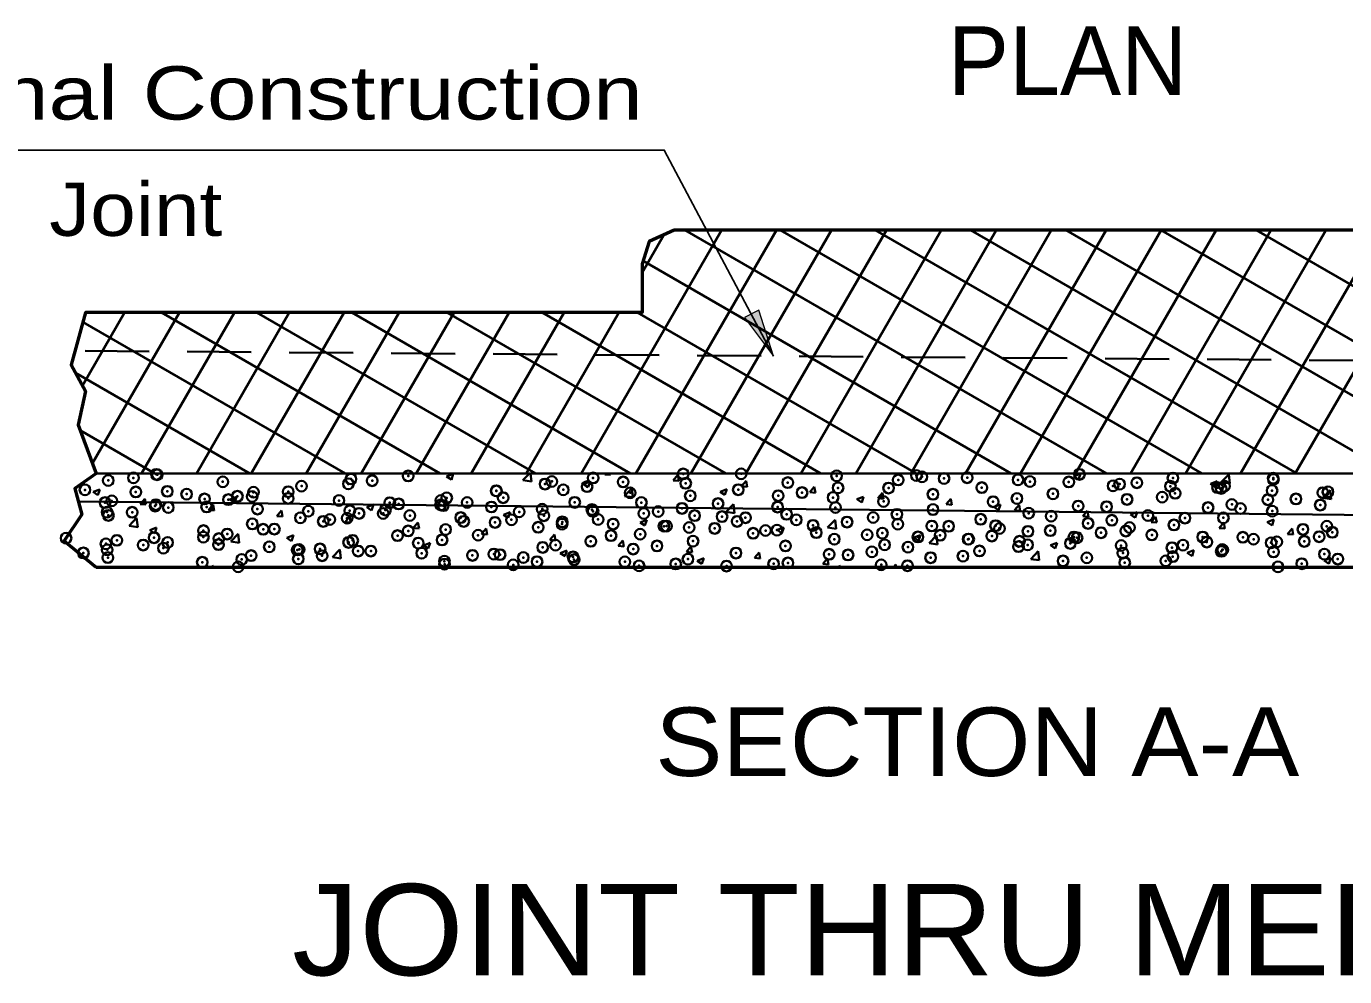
# Model space of a CAD drawing. Extents: x 14 to 49.3, y 28 to 50.
# Drawn here: x 18.676 to 22.139, y 39.449 to 41.946 of the extents above; entities that cross this region are included whole.
import ezdxf

# ---------------------------------------------------------------- set-up
doc = ezdxf.new("R2010")
doc.units = 0
doc.header["$LTSCALE"] = 0.056
doc.header["$PDMODE"] = 32
doc.header["$PDSIZE"] = 0.028
doc.linetypes.add('MEDIUM_DASHED', pattern=[4.5, 3, -1.5])
for name, color, linetype, lineweight in [('1', 7, 'Continuous', 35), ('2', 7, 'MEDIUM_DASHED', 35), ('3', 7, 'Continuous', 13)]:
    doc.layers.add(name, color=color, linetype=linetype, lineweight=lineweight)

msp = doc.modelspace()

# ---------------------------------------------------------------- hatches: boundary and pattern name
at = {"layer": '3'}
msp.add_hatch(color=256, dxfattribs=at).paths.add_polyline_path([(20.59983, 41.20042), (20.56292, 41.18133), (20.63883, 41.07983), (20.63883, 41.07983)])

# ---------------------------------------------------------------- linework, layer by layer
at = {"layer": '1', "lineweight": 40}
for p, q in [((20.13308, 40.77142), (20.50208, 41.41067)), ((20.27742, 40.77142), (20.6465, 41.41067)), ((20.29342, 41.29925), (20.35075, 41.3985)), ((20.40617, 41.41067), (21.51342, 40.77142)), ((20.42175, 40.77142), (20.79083, 41.41067)), ((20.56608, 40.77142), (20.93517, 41.41067)), ((20.65617, 41.41067), (21.76342, 40.77142)), ((20.71042, 40.77142), (21.0795, 41.41067)), ((20.85475, 40.77142), (21.22383, 41.41067)), ((20.90617, 41.41067), (22.01342, 40.77142)), ((20.99908, 40.77142), (21.36817, 41.41067)), ((21.14342, 40.77142), (21.5125, 41.41067)), ((21.15617, 41.41067), (22.26342, 40.77142)), ((21.28775, 40.77142), (21.65683, 41.41067)), ((21.40617, 41.41067), (22.51342, 40.77142)), ((21.43208, 40.77142), (21.80117, 41.41067)), ((21.57642, 40.77142), (21.9455, 41.41067)), ((21.65617, 41.41067), (22.76342, 40.77142)), ((21.72075, 40.77142), (22.08983, 41.41067)), ((21.86508, 40.77142), (22.23417, 41.41067)), ((21.90617, 41.41067), (23.01342, 40.77142)), ((22.00942, 40.77142), (22.3785, 41.41067)), ((20.29592, 41.33), (21.26342, 40.77142)), ((18.82317, 41.00267), (18.93383, 41.19433)), ((18.8495, 40.79833), (19.07817, 41.19433)), ((18.97833, 40.77142), (19.2225, 41.19433)), ((19.03092, 41.19433), (19.76342, 40.77142)), ((19.12267, 40.77142), (19.36683, 41.19433)), ((19.267, 40.77142), (19.51117, 41.19433)), ((19.28092, 41.19433), (20.01342, 40.77142)), ((19.41133, 40.77142), (19.6555, 41.19433)), ((19.53092, 41.19433), (20.26342, 40.77142)), ((19.55575, 40.77142), (19.79983, 41.19433)), ((19.70008, 40.77142), (19.94417, 41.19433)), ((19.78092, 41.19433), (20.51342, 40.77142)), ((19.84442, 40.77142), (20.0885, 41.19433)), ((19.98875, 40.77142), (20.23283, 41.19433)), ((20.03092, 41.19433), (20.76342, 40.77142)), ((20.28092, 41.19433), (21.01342, 40.77142)), ((18.82442, 41.16925), (19.51342, 40.77142)), ((18.80492, 41.03617), (19.26342, 40.77142)), ((18.818, 40.88425), (19.01342, 40.77142))]:
    msp.add_line(p, q, dxfattribs=at)
at = {"layer": '1'}
for p, q in [((23.80842, 40.77142), (18.85933, 40.77142)), ((19.78008, 40.7635), (19.79758, 40.77025)), ((19.78008, 40.7635), (19.7925, 40.75517)), ((19.79258, 40.75508), (19.79758, 40.77025)), ((19.98042, 40.7535), (19.99767, 40.77142)), ((20.00267, 40.75008), (20.00017, 40.77142)), ((20.00267, 40.75008), (20.00017, 40.77142)), ((20.19575, 40.769), (20.19792, 40.77142)), ((20.19575, 40.769), (20.21075, 40.76767)), ((20.21075, 40.76767), (20.21, 40.77142)), ((20.37508, 40.75325), (20.38717, 40.76767)), ((20.39008, 40.752), (20.38717, 40.76767)), ((21.42725, 40.76408), (21.44475, 40.77075)), ((21.42725, 40.76408), (21.43975, 40.75567)), ((21.43975, 40.75567), (21.44483, 40.77075)), ((21.815, 40.74875), (21.83442, 40.76908)), ((21.83725, 40.74533), (21.83442, 40.769)), ((18.8515, 40.72292), (18.869, 40.72967)), ((18.86392, 40.7145), (18.869, 40.72967)), ((19.98042, 40.7535), (20.00267, 40.75008)), ((20.13942, 40.7435), (20.15692, 40.75025)), ((20.13942, 40.7435), (20.15183, 40.73508)), ((20.15183, 40.73508), (20.15692, 40.75025)), ((20.24725, 40.71208), (20.26675, 40.73242)), ((20.2695, 40.70867), (20.26675, 40.73242)), ((20.37508, 40.75325), (20.39, 40.752)), ((20.49867, 40.7235), (20.51617, 40.73017)), ((20.49867, 40.7235), (20.51108, 40.71508)), ((20.51108, 40.71508), (20.51617, 40.73017)), ((20.55442, 40.73758), (20.5665, 40.75192)), ((20.55442, 40.73758), (20.56933, 40.73625)), ((20.56933, 40.73625), (20.5665, 40.75192)), ((20.73375, 40.72192), (20.74575, 40.73625)), ((20.74867, 40.72058), (20.74575, 40.73625)), ((21.78658, 40.744), (21.80408, 40.75075)), ((21.78658, 40.744), (21.799, 40.73567)), ((21.799, 40.73567), (21.80408, 40.75075)), ((21.815, 40.74875), (21.83717, 40.74533)), ((22.08175, 40.70733), (22.10125, 40.72767)), ((22.104, 40.70392), (22.10125, 40.72767)), ((18.80667, 40.71917), (18.808, 40.72075)), ((18.81092, 40.70508), (18.808, 40.72075)), ((18.81042, 40.70517), (18.81092, 40.70508)), ((23.81192, 40.64508), (18.81242, 40.69783)), ((18.8515, 40.72292), (18.86392, 40.7145)), ((18.97525, 40.69075), (18.98733, 40.70508)), ((18.97525, 40.69075), (18.99025, 40.68942)), ((18.99025, 40.68942), (18.98733, 40.70508)), ((19.15458, 40.67508), (19.16667, 40.68942)), ((19.1695, 40.67375), (19.16667, 40.68942)), ((19.21075, 40.70292), (19.22825, 40.70958)), ((19.21075, 40.70292), (19.22317, 40.6945)), ((19.22325, 40.6945), (19.22825, 40.70958)), ((19.57008, 40.68292), (19.58758, 40.68958)), ((19.5825, 40.6745), (19.58758, 40.68958)), ((20.24725, 40.71208), (20.2695, 40.70867)), ((20.51408, 40.67075), (20.5335, 40.691)), ((20.53633, 40.66725), (20.53358, 40.691)), ((20.73375, 40.72192), (20.74867, 40.72058)), ((20.85792, 40.70342), (20.87542, 40.71017)), ((20.85792, 40.70342), (20.87042, 40.69508)), ((20.87042, 40.69508), (20.8755, 40.71017)), ((20.91308, 40.70625), (20.92508, 40.72058)), ((20.91308, 40.70625), (20.928, 40.70492)), ((20.928, 40.70492), (20.92508, 40.72058)), ((21.09233, 40.6905), (21.10442, 40.70492)), ((21.09233, 40.6905), (21.10733, 40.68925)), ((21.10733, 40.68925), (21.10442, 40.70492)), ((21.21725, 40.68342), (21.23475, 40.69017)), ((21.22967, 40.675), (21.23475, 40.69017)), ((21.27167, 40.67483), (21.28375, 40.68917)), ((21.28667, 40.6735), (21.28375, 40.68917)), ((22.08175, 40.70733), (22.104, 40.70392)), ((18.94633, 40.63408), (18.96583, 40.65442)), ((18.96858, 40.63067), (18.96583, 40.65442)), ((19.15458, 40.67508), (19.1695, 40.67375)), ((19.33392, 40.65933), (19.34592, 40.67375)), ((19.33392, 40.65933), (19.34883, 40.65808)), ((19.34883, 40.65808), (19.346, 40.67375)), ((19.51325, 40.64367), (19.52525, 40.658)), ((19.52817, 40.64233), (19.52525, 40.658)), ((19.57008, 40.68292), (19.5825, 40.6745)), ((19.92933, 40.66283), (19.94683, 40.66958)), ((19.92933, 40.66283), (19.94175, 40.6545)), ((19.94175, 40.6545), (19.94683, 40.66958)), ((20.51408, 40.67075), (20.53633, 40.66725)), ((21.21725, 40.68342), (21.22967, 40.675)), ((21.27167, 40.67483), (21.28658, 40.6735)), ((21.451, 40.65917), (21.463, 40.6735)), ((21.451, 40.65917), (21.46592, 40.65783)), ((21.46592, 40.65783), (21.46308, 40.6735)), ((21.5765, 40.66342), (21.594, 40.67008)), ((21.5765, 40.66342), (21.58892, 40.655)), ((21.589, 40.655), (21.594, 40.67008)), ((21.63033, 40.6435), (21.64233, 40.65783)), ((21.64525, 40.64217), (21.64233, 40.65783)), ((18.94633, 40.63408), (18.96858, 40.63067)), ((19.00075, 40.62225), (19.01825, 40.629)), ((19.00075, 40.62225), (19.01317, 40.61392)), ((19.01317, 40.61392), (19.01825, 40.629)), ((19.51325, 40.64367), (19.52817, 40.64233)), ((19.6925, 40.628), (19.70458, 40.64233)), ((19.6925, 40.628), (19.7075, 40.62667)), ((19.7075, 40.62667), (19.70458, 40.64233)), ((19.87183, 40.61233), (19.88392, 40.62667)), ((19.88683, 40.611), (19.88392, 40.62667)), ((20.28858, 40.64283), (20.30608, 40.64958)), ((20.28858, 40.64283), (20.30108, 40.63442)), ((20.30108, 40.63442), (20.30617, 40.64958)), ((20.64792, 40.62283), (20.66542, 40.6295)), ((20.64792, 40.62283), (20.66033, 40.61442)), ((20.66033, 40.61442), (20.66542, 40.6295)), ((20.78083, 40.62933), (20.80033, 40.64967)), ((20.78083, 40.62933), (20.80308, 40.62592)), ((20.80308, 40.62592), (20.80033, 40.64967)), ((21.63033, 40.6435), (21.64525, 40.64217)), ((21.80958, 40.62775), (21.82167, 40.64217)), ((21.80958, 40.62775), (21.82458, 40.6265)), ((21.82458, 40.6265), (21.82167, 40.64217)), ((21.93583, 40.64342), (21.95333, 40.65008)), ((21.93583, 40.64342), (21.94825, 40.635)), ((21.94825, 40.635), (21.95333, 40.65008)), ((21.98892, 40.61208), (22.001, 40.62642)), ((22.00392, 40.61075), (22.001, 40.62642)), ((19.21317, 40.59275), (19.23267, 40.613)), ((19.21317, 40.59275), (19.23542, 40.58925)), ((19.23542, 40.58925), (19.23267, 40.613)), ((19.36, 40.60225), (19.3775, 40.609)), ((19.36, 40.60225), (19.37242, 40.59383)), ((19.37242, 40.59383), (19.3775, 40.609)), ((19.71925, 40.58225), (19.73675, 40.58892)), ((19.73175, 40.57383), (19.73675, 40.58892)), ((19.87183, 40.61233), (19.88675, 40.611)), ((20.05117, 40.59658), (20.06325, 40.611)), ((20.05117, 40.59658), (20.06608, 40.59533)), ((20.06608, 40.59533), (20.06325, 40.611)), ((20.2305, 40.58092), (20.2425, 40.59525)), ((20.24542, 40.57958), (20.2425, 40.59525)), ((21.00717, 40.60283), (21.02467, 40.6095)), ((21.00717, 40.60283), (21.01958, 40.59442)), ((21.01958, 40.59442), (21.02467, 40.6095)), ((21.04767, 40.588), (21.06717, 40.60825)), ((21.04767, 40.588), (21.06992, 40.5845)), ((21.06992, 40.5845), (21.06717, 40.60825)), ((21.3665, 40.58275), (21.384, 40.5895)), ((21.37892, 40.57442), (21.384, 40.5895)), ((21.98892, 40.61208), (22.00392, 40.61075)), ((19.48, 40.55133), (19.49942, 40.57167)), ((19.48, 40.55133), (19.50217, 40.54792)), ((19.50225, 40.54792), (19.49942, 40.57167)), ((19.71925, 40.58225), (19.73175, 40.57383)), ((20.07858, 40.56217), (20.09608, 40.56892)), ((20.07858, 40.56217), (20.091, 40.55383)), ((20.091, 40.55383), (20.09608, 40.56892)), ((20.2305, 40.58092), (20.24542, 40.57958)), ((20.40975, 40.56525), (20.42183, 40.57958)), ((20.40975, 40.56525), (20.42475, 40.56392)), ((20.42475, 40.56392), (20.42183, 40.57958)), ((20.58908, 40.5495), (20.60117, 40.56392)), ((20.60408, 40.54825), (20.60117, 40.56392)), ((21.3145, 40.54658), (21.334, 40.56692)), ((21.33675, 40.54317), (21.334, 40.56692)), ((21.3665, 40.58275), (21.37892, 40.57442)), ((21.72575, 40.56275), (21.74325, 40.5695)), ((21.72575, 40.56275), (21.73817, 40.55433)), ((21.73817, 40.55433), (21.74325, 40.5695)), ((19.16033, 40.52558), (19.16742, 40.52833)), ((19.1665, 40.52558), (19.16742, 40.52833)), ((19.76175, 40.52558), (19.76625, 40.53025)), ((19.76683, 40.52558), (19.76625, 40.53025)), ((20.43783, 40.54217), (20.45533, 40.54892)), ((20.43783, 40.54217), (20.45025, 40.53383)), ((20.45025, 40.53383), (20.45533, 40.54892)), ((20.58908, 40.5495), (20.60408, 40.54825)), ((20.76842, 40.53383), (20.7805, 40.54825)), ((20.76842, 40.53383), (20.78333, 40.53258)), ((20.78333, 40.53258), (20.7805, 40.54825)), ((20.80608, 40.52558), (20.81458, 40.52892)), ((20.8135, 40.52558), (20.81467, 40.52892)), ((20.954, 40.52558), (20.95975, 40.5325)), ((20.96108, 40.52558), (20.95983, 40.5325)), ((21.3145, 40.54658), (21.33675, 40.54317)), ((22.085, 40.54275), (22.1025, 40.54942)), ((22.085, 40.54275), (22.0975, 40.53433)), ((22.0975, 40.53433), (22.1025, 40.54942))]:
    msp.add_line(p, q, dxfattribs=at)
at = {"layer": '1', "lineweight": 53}
msp.add_line((18.85933, 40.52558), (23.81775, 40.52558), dxfattribs=at)
for points in [[(23.799, 41.17467), (22.55233, 41.17467), (22.55233, 41.35167), (22.52425, 41.37133), (22.48675, 41.41067), (20.37783, 41.41067), (20.31217, 41.38117), (20.29342, 41.32217), (20.29342, 41.19433), (18.83125, 41.19433), (18.79375, 41.05667), (18.83125, 40.98783), (18.8125, 40.89933), (18.85933, 40.77142)], [(18.85933, 40.77142), (18.80308, 40.73208), (18.82183, 40.66325), (18.775, 40.59442), (18.85933, 40.52558)]]:
    msp.add_lwpolyline(points, dxfattribs=at)
at = {"layer": '1'}
for p in [(18.89117, 40.75292), (18.95733, 40.75975), (19.0175, 40.76892), (19.01992, 40.768), (19.19217, 40.74942), (19.52192, 40.74408), (19.52875, 40.75683), (19.5845, 40.75233), (19.67917, 40.76483), (20.05658, 40.75042), (20.16483, 40.75958), (20.24375, 40.74917), (20.40158, 40.77), (20.40808, 40.74558), (20.55392, 40.77058), (20.67617, 40.74742), (20.8045, 40.765), (20.96617, 40.75433), (21.01408, 40.76592), (21.02875, 40.76258), (21.08675, 40.75817), (21.1475, 40.76025), (21.281, 40.75458), (21.31225, 40.75017), (21.41442, 40.749), (21.44208, 40.76892), (21.59325, 40.747), (21.688, 40.75942), (21.95125, 40.75917), (21.95183, 40.75567), (18.83008, 40.72833), (18.9635, 40.72275), (19.04633, 40.72442), (19.097, 40.71708), (19.23042, 40.71142), (19.26933, 40.71083), (19.27267, 40.72208), (19.364, 40.72333), (19.39892, 40.73808), (19.91025, 40.72592), (19.91083, 40.72542), (20.03858, 40.74358), (20.08642, 40.7285), (20.149, 40.73675), (20.26233, 40.72058), (20.42, 40.71267), (20.54625, 40.72867), (20.651, 40.71283), (20.71358, 40.72108), (20.80825, 40.73358), (20.941, 40.73317), (21.05758, 40.71658), (21.18592, 40.73417), (21.37283, 40.71792), (21.53067, 40.73875), (21.54792, 40.74333), (21.68133, 40.73767), (21.69367, 40.71925), (21.80542, 40.73417), (21.81475, 40.73208), (21.8235, 40.738), (21.94825, 40.72642), (22.08167, 40.72075), (22.09525, 40.72308), (18.88283, 40.69475), (18.90058, 40.69942), (19.01442, 40.68575), (19.01625, 40.68917), (19.04883, 40.68183), (19.14425, 40.7045), (19.14967, 40.6835), (19.20675, 40.70258), (19.28317, 40.67783), (19.36392, 40.70583), (19.49733, 40.70017), (19.61925, 40.67533), (19.63083, 40.6945), (19.65408, 40.69117), (19.76425, 40.68892), (19.765, 40.70033), (19.77133, 40.687), (19.78033, 40.70717), (19.83392, 40.69525), (19.89775, 40.68325), (19.92858, 40.70767), (20.03117, 40.67758), (20.1165, 40.6955), (20.16183, 40.67633), (20.29167, 40.69508), (20.39842, 40.67958), (20.49308, 40.69208), (20.64942, 40.68308), (20.79517, 40.70817), (20.80142, 40.68183), (20.92775, 40.69783), (21.05767, 40.6765), (21.21558, 40.69725), (21.27817, 40.7055), (21.439, 40.68567), (21.51383, 40.68408), (21.56742, 40.70325), (21.65967, 40.70917), (21.78008, 40.68167), (21.84267, 40.68983), (21.86533, 40.67925), (21.93733, 40.70233), (22.01117, 40.70433), (22.07508, 40.68842), (18.88817, 40.66975), (18.89158, 40.66117), (18.95417, 40.66933), (19.39592, 40.65483), (19.41658, 40.67225), (19.45617, 40.6455), (19.47342, 40.65033), (19.51875, 40.65375), (19.52575, 40.67358), (19.55008, 40.66658), (19.61342, 40.66625), (19.6835, 40.66092), (19.817, 40.65533), (19.82492, 40.6455), (19.90717, 40.64275), (19.95042, 40.64967), (19.97075, 40.6705), (20.0355, 40.66033), (20.08392, 40.644), (20.16467, 40.672), (20.17792, 40.65058), (20.29808, 40.66633), (20.33583, 40.67142), (20.43158, 40.66067), (20.50358, 40.65808), (20.54325, 40.64542), (20.565, 40.65508), (20.67308, 40.66417), (20.6985, 40.64942), (20.83192, 40.64375), (20.90042, 40.65575), (20.963, 40.664), (21.18292, 40.65092), (21.30917, 40.66692), (21.368, 40.65908), (21.46492, 40.64017), (21.5275, 40.64842), (21.62217, 40.66083), (21.7195, 40.65425), (21.8205, 40.65483), (21.94883, 40.67242), (19.14125, 40.62125), (19.20358, 40.61225), (19.26958, 40.63883), (19.29825, 40.62475), (19.32758, 40.62525), (19.65108, 40.608), (19.67908, 40.62042), (19.77733, 40.624), (19.86283, 40.60908), (20.02067, 40.62992), (20.08325, 40.63817), (20.212, 40.608), (20.21733, 40.63842), (20.28858, 40.61183), (20.35083, 40.63275), (20.35775, 40.63308), (20.417, 40.62942), (20.48425, 40.62708), (20.58525, 40.61425), (20.61775, 40.6215), (20.64783, 40.6225), (20.7425, 40.635), (20.75117, 40.61583), (20.88467, 40.61017), (20.92467, 40.61458), (20.96533, 40.63817), (21.0545, 40.63333), (21.07642, 40.609), (21.09883, 40.6325), (21.21233, 40.60692), (21.22225, 40.63408), (21.23225, 40.62683), (21.30708, 40.61933), (21.36575, 40.62125), (21.49917, 40.61558), (21.56433, 40.62008), (21.57375, 40.62925), (21.63267, 40.60992), (21.69058, 40.63608), (22.0295, 40.6245), (22.09208, 40.63275), (22.10658, 40.61683), (18.78033, 40.60125), (18.88508, 40.5865), (18.88842, 40.57075), (18.91383, 40.59567), (18.98308, 40.58325), (19.01142, 40.6025), (19.036, 40.57525), (19.04725, 40.59), (19.141, 40.604), (19.18075, 40.58433), (19.18183, 40.60025), (19.31417, 40.57875), (19.39283, 40.57167), (19.44758, 40.57308), (19.52267, 40.59033), (19.53333, 40.59542), (19.7055, 40.58842), (19.76808, 40.59667), (20.0325, 40.57708), (20.06617, 40.583), (20.15875, 40.59308), (20.27008, 40.57275), (20.33267, 40.581), (20.42733, 40.5935), (20.67008, 40.581), (20.79842, 40.59858), (20.93067, 40.584), (20.99192, 40.57783), (21.01808, 40.60458), (21.14975, 40.59867), (21.1515, 40.59892), (21.28217, 40.57917), (21.285, 40.59325), (21.30617, 40.58375), (21.41842, 40.58767), (21.42792, 40.60417), (21.436, 40.60242), (21.55192, 40.582), (21.68533, 40.57633), (21.71433, 40.583), (21.76608, 40.60433), (21.77692, 40.59125), (21.81742, 40.57158), (21.81883, 40.57075), (21.87158, 40.60375), (21.89958, 40.59867), (21.94575, 40.58917), (21.96083, 40.59175), (22.033, 40.593), (22.07208, 40.60517), (18.82583, 40.5625), (18.89025, 40.55025), (19.13817, 40.538), (19.24175, 40.54533), (19.26658, 40.55558), (19.3875, 40.57042), (19.39042, 40.54692), (19.453, 40.55517), (19.54767, 40.56758), (19.58108, 40.56742), (19.7145, 40.56183), (19.77425, 40.54075), (19.848, 40.55617), (19.90417, 40.5595), (19.92042, 40.558), (19.98142, 40.5505), (20.0175, 40.5395), (20.11217, 40.552), (20.11492, 40.54492), (20.24833, 40.53925), (20.41392, 40.54625), (20.54017, 40.56225), (20.67675, 40.53633), (20.78483, 40.559), (20.83458, 40.55717), (20.89717, 40.56542), (21.0515, 40.55008), (21.13633, 40.55417), (21.17983, 40.56775), (21.39917, 40.5415), (21.46175, 40.54975), (21.55642, 40.56225), (21.56133, 40.53683), (21.66925, 40.54175), (21.68758, 40.55283), (21.815, 40.56675), (21.95225, 40.56508), (22.08575, 40.55942), (22.121, 40.54658), (19.2325, 40.52608), (19.77458, 40.533), (19.95492, 40.53125), (20.28558, 40.52867), (20.38183, 40.53358), (20.51525, 40.528), (20.63908, 40.53392), (20.92167, 40.53133), (20.99058, 40.52908), (21.96375, 40.52592), (22.02633, 40.53417)]:
    msp.add_point(p, dxfattribs=at)
at = {"layer": '2'}
msp.add_line((23.82217, 41.05592), (18.80383, 41.09367), dxfattribs=at)
at = {"layer": '3', "lineweight": 25}
msp.add_lwpolyline([(20.63883, 41.07983), (20.35175, 41.62092), (18.00467, 41.62092)], dxfattribs=at)
at = {"layer": '3'}
msp.add_lwpolyline([(20.59983, 41.20042), (20.56292, 41.18133), (20.63883, 41.07983), (20.63883, 41.07983)], close=True, dxfattribs=at)

# ---------------------------------------------------------------- texts
msp.add_text('PLAN', height=0.18, dxfattribs=at).set_placement((21.09675, 41.76625))
for s, height, width, p in [('Optional Construction', 0.14, 1.25, (18.04492, 41.70133)), ('Joint', 0.14, 1.15, (18.73617, 41.39575)), ('SECTION A-A', 0.18, 1.1, (20.32808, 39.97642)), ('JOINT THRU MEDIAN', 0.24, 1.1, (19.37392, 39.45258))]:
    msp.add_text(s, height=height, dxfattribs=dict(at, width=width)).set_placement(p)

doc.saveas('drawing.dxf')
